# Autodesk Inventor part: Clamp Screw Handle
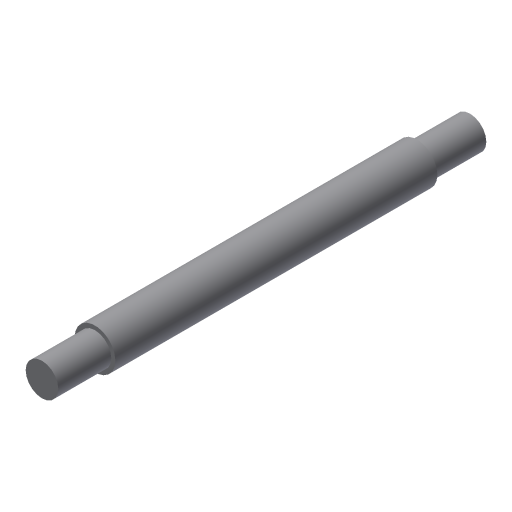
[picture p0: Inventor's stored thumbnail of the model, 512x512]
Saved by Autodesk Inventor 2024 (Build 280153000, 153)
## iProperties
Shininess: 77.0
Length Units: 11269
Angle Units: 11279
Time Units: 11290
Mass Units: 11283
Length Display Precision: 3
Angle Display Precision: 2
Compacted: True
Created: 2002-02
Part Number: Clamp Screw Handle
Document SubType Name: Modeling
Designer: ***
Density: 1 g/cm^3
Material: Generic
Mass: 7.51155 g
Surface Area: 32.9239 cm^2
Volume: 7.51155 cm^3
Appearance: Default
Density: 0.0
Volumn: 0.0
Area: 0.0
PropertySet Name: Model Information
Control State: 0
Master: False
Checked Out: False
Author: ***
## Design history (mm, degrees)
sketch "Sketch1"
  geometry: L1 (0, 105)-(4, 105); L2 (4, 105)-(4, 92); L3 (4, 92)-(5, 92); L4 (5, 92)-(5, 13); L5 (5, 13)-(4, 13); L6 (4, 13)-(4, 0); L7 (4, 0)-(0, 0); L8 (0, 0)-(0, 105)
  constraints: 16 end point, 5 parallel, 2 equal length, 1 collinear, 1 horizontal, 1 perpendicular
  dimensions: "d0" = 10 diameter of L4 L8; "d1" = 8 diameter of L2 L8; "d2" = 13 distance of L1.end L2.end; "d3" = 79 distance of L3.end L4.end
revolve "Revolution1" sketch "Sketch1" stored, may be unused: angle "d4" = 90 deg
body "Solid1"
